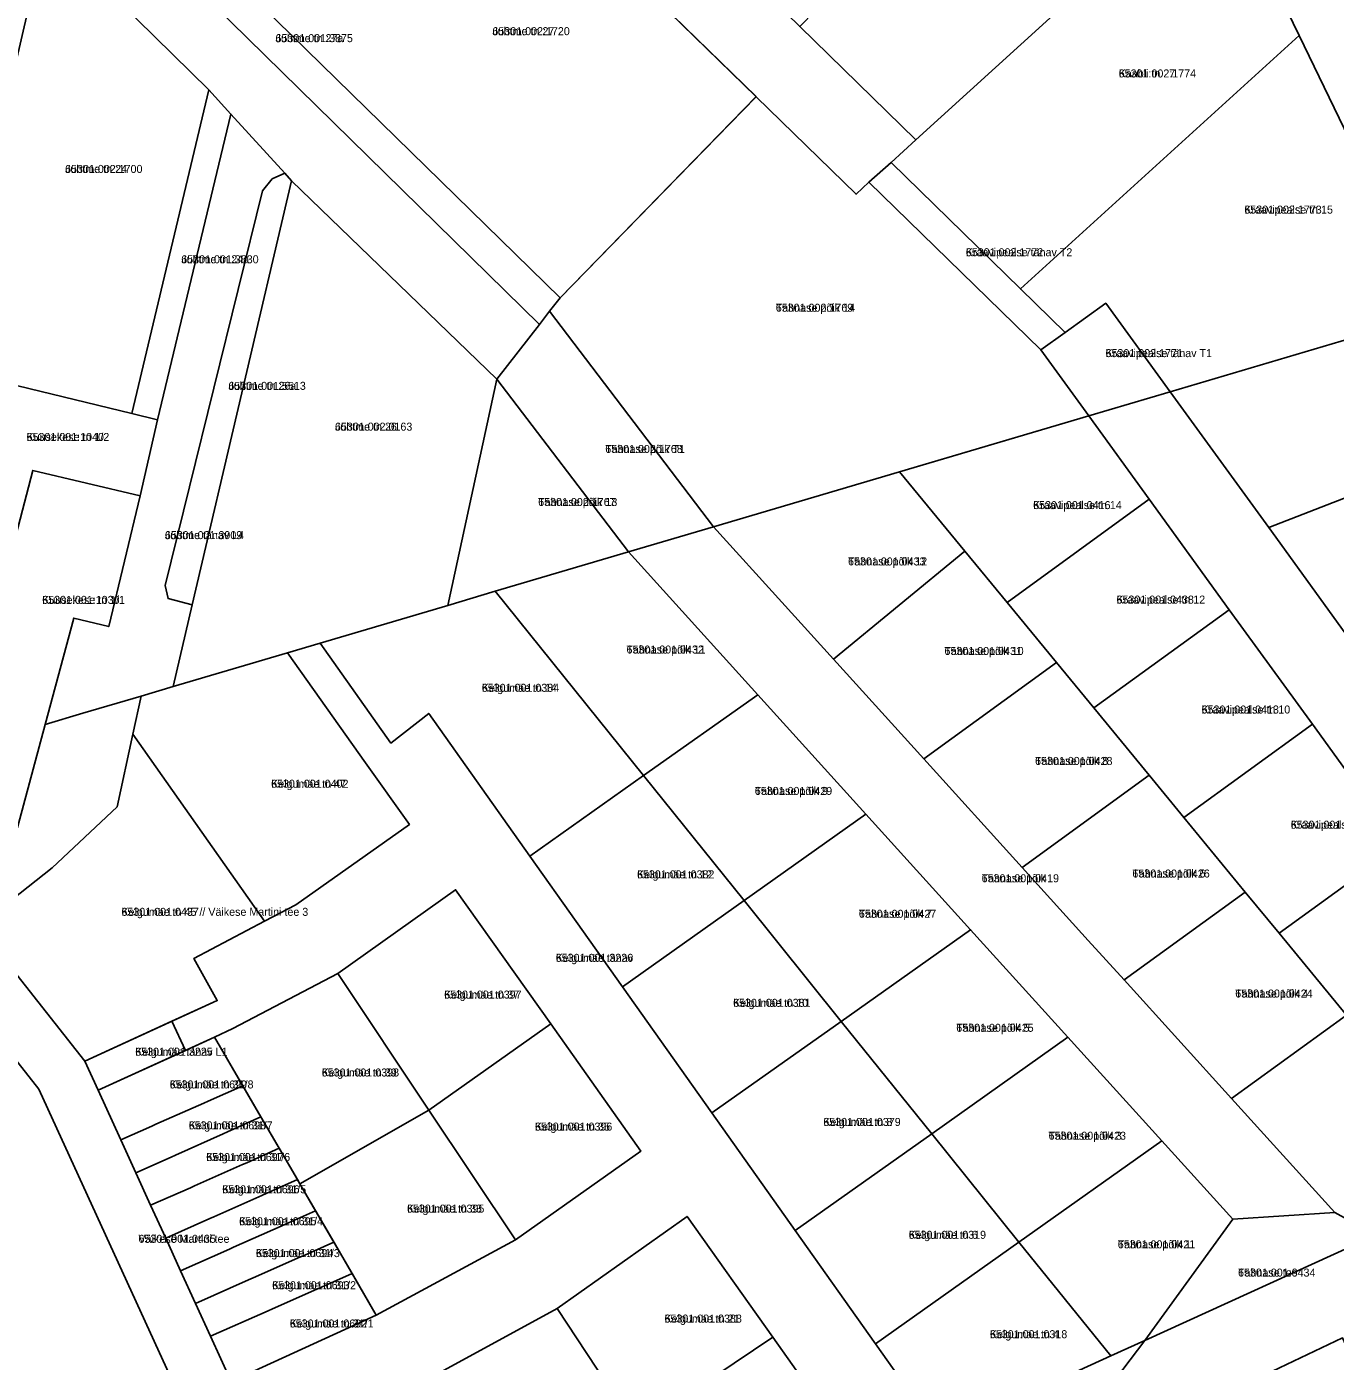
# Model space of a CAD drawing. Extents: x 543236 to 563717, y 6566033 to 6588992.
# Drawn here: x 546441.8 to 546687, y 6585249.2 to 6585499.3 of the extents above; entities that cross this region are included whole.
import ezdxf

# ---------------------------------------------------------------- set-up
doc = ezdxf.new("R2010")
doc.units = 0
for name, color, linetype in [('L_AADRESS', 7, 'Continuous'), ('PIIR', 7, 'Continuous'), ('TUNNUS', 7, 'Continuous')]:
    doc.layers.add(name, color=color, linetype=linetype)

msp = doc.modelspace()

# ---------------------------------------------------------------- linework, layer by layer
at = {"layer": 'PIIR'}
for points in [[(546727.56, 6585734.34), (546736.38, 6585744.23), (546742.19, 6585738.52), (547036.09, 6585449.99), (546820.76, 6585258.14), (546786.32, 6585314.76), (546705.5, 6585445.49), (546680.25, 6585497.64), (546664.84, 6585529.42), (546597.49, 6585563.12), (546613.01, 6585604.01)], [(546357.12, 6585624.43), (546359.63, 6585618.5), (546403.76, 6585575.17), (546410.64, 6585568.43), (546473.54, 6585506.66), (546537.87, 6585443.5), (546529.9, 6585433.25), (546491.44, 6585470.41), (546490.13, 6585471.85), (546480.05, 6585482.92), (546475.94, 6585487.45), (546445.52, 6585517.35), (546415.03, 6585547.94), (546403.82, 6585560.18), (546386.95, 6585577.03), (546377.64, 6585586.13), (546368.4, 6585595.16), (546359.11, 6585604.18), (546354.05, 6585609.18), (546349.17, 6585611.38)], [(546473.54, 6585506.66), (546513.47, 6585549.28), (546516.06, 6585546.9), (546483.31, 6585511.95), (546480.25, 6585508.68), (546541.76, 6585448.5), (546539.77, 6585445.95), (546537.87, 6585443.5)], [(546516.06, 6585546.9), (546578.48, 6585486.19), (546541.76, 6585448.5), (546480.25, 6585508.68), (546483.31, 6585511.95)], [(546628.84, 6585542.5), (546653.19, 6585518.82), (546608.42, 6585478.09), (546586.66, 6585499.3), (546620.46, 6585533.91)], [(546603.76, 6585473.84), (546608.42, 6585478.09), (546653.19, 6585518.82), (546664.84, 6585529.42), (546680.25, 6585497.64), (546628, 6585450.13)], [(546428.12, 6585448.52), (546422.02, 6585461.28), (546433.75, 6585466.89), (546445.52, 6585517.35), (546475.94, 6585487.45), (546461.46, 6585426.8), (546435.69, 6585433.02)], [(546628, 6585450.13), (546680.25, 6585497.64), (546705.5, 6585445.49), (546701.61, 6585444.34), (546656.07, 6585430.87), (546644, 6585447.47), (546636.37, 6585441.96)], [(546461.46, 6585426.8), (546475.94, 6585487.45), (546480.05, 6585482.92), (546466.3, 6585425.58)], [(546578.47, 6585486.17), (546597.22, 6585467.9), (546599.63, 6585470.14), (546631.85, 6585438.7), (546640.82, 6585426.36), (546605.38, 6585415.88), (546570.52, 6585405.57), (546539.77, 6585445.95), (546541.76, 6585448.5)], [(546480.05, 6585482.92), (546490.13, 6585471.85), (546487.8, 6585470.78), (546485.99, 6585468.5), (546467.75, 6585394.53), (546468.29, 6585392.11), (546472.81, 6585390.95), (546469.21, 6585375.61), (546463.23, 6585373.84), (546452.31, 6585370.61), (546445.23, 6585368.52), (546450.6, 6585388.45), (546457.16, 6585386.87), (546463.02, 6585411.39), (546466.3, 6585425.58)], [(546599.63, 6585470.14), (546603.76, 6585473.84), (546628, 6585450.13), (546636.37, 6585441.96), (546631.85, 6585438.7)], [(546491.44, 6585470.41), (546472.81, 6585390.95), (546468.29, 6585392.11), (546467.75, 6585394.53), (546485.99, 6585468.5), (546487.8, 6585470.78), (546490.13, 6585471.85)], [(546491.44, 6585470.41), (546529.9, 6585433.25), (546520.72, 6585390.84), (546496.76, 6585383.76), (546490.68, 6585381.96), (546469.21, 6585375.61), (546472.81, 6585390.95)], [(546539.77, 6585445.95), (546570.52, 6585405.57), (546554.56, 6585400.85), (546529.9, 6585433.25), (546537.87, 6585443.5)], [(546631.85, 6585438.7), (546636.37, 6585441.96), (546644, 6585447.47), (546656.07, 6585430.87), (546640.82, 6585426.36)], [(546656.07, 6585430.87), (546701.61, 6585444.34), (546715.75, 6585421.44), (546674.54, 6585405.4)], [(546529.9, 6585433.25), (546554.56, 6585400.85), (546529.59, 6585393.47), (546520.72, 6585390.84)], [(546426.36, 6585352.75), (546417.23, 6585361.97), (546435.69, 6585433.02), (546461.46, 6585426.8), (546466.3, 6585425.58), (546463.02, 6585411.39), (546442.91, 6585416.14)], [(546640.82, 6585426.36), (546656.07, 6585430.87), (546674.54, 6585405.4), (546692.13, 6585381.14), (546711.01, 6585355.1), (546730.57, 6585328.13), (546751.73, 6585298.95), (546737.81, 6585292.59), (546716.82, 6585321.54), (546699.19, 6585345.85), (546682.73, 6585368.55), (546667.16, 6585390.03), (546652.17, 6585410.71)], [(546605.38, 6585415.88), (546613.6, 6585418.31), (546640.82, 6585426.36), (546652.17, 6585410.71), (546625.52, 6585391.39), (546617.61, 6585401.01)], [(546674.54, 6585405.4), (546715.75, 6585421.44), (546729.96, 6585398.42), (546692.13, 6585381.14)], [(546426.36, 6585352.75), (546442.91, 6585416.14), (546463.02, 6585411.39), (546457.16, 6585386.87), (546450.6, 6585388.45), (546445.23, 6585368.52), (546440.03, 6585349.21)], [(546570.52, 6585405.57), (546605.38, 6585415.88), (546617.61, 6585401.01), (546592.99, 6585380.76), (546583.3, 6585391.46)], [(546625.52, 6585391.39), (546652.17, 6585410.71), (546667.16, 6585390.03), (546641.77, 6585371.63), (546634.78, 6585380.13)], [(546554.56, 6585400.85), (546564.14, 6585403.68), (546570.52, 6585405.57), (546583.3, 6585391.46), (546592.99, 6585380.76), (546609.9, 6585362.08), (546628.33, 6585341.73), (546640.72, 6585328.05), (546647.43, 6585320.64), (546667.55, 6585298.42), (546686.92, 6585277.02), (546667.82, 6585275.77), (546654.5, 6585290.48), (546636.92, 6585309.89), (546618.67, 6585330.05), (546599.07, 6585351.7), (546578.79, 6585374.1)], [(546529.59, 6585393.47), (546554.56, 6585400.85), (546578.79, 6585374.1), (546557.38, 6585358.92)], [(546592.99, 6585380.76), (546617.61, 6585401.01), (546625.52, 6585391.39), (546634.78, 6585380.13), (546609.9, 6585362.08)], [(546496.76, 6585383.76), (546520.72, 6585390.84), (546529.59, 6585393.47), (546557.38, 6585358.92), (546536.09, 6585343.83), (546517.13, 6585370.58), (546510.03, 6585365.03)], [(546641.77, 6585371.63), (546667.16, 6585390.03), (546682.73, 6585368.55), (546658.66, 6585351.1), (546652.15, 6585359.01)], [(546469.21, 6585375.61), (546490.68, 6585381.96), (546505.29, 6585361.35), (546513.5, 6585349.77), (546492.22, 6585334.69), (546486.37, 6585331.62), (546461.69, 6585366.71), (546463.23, 6585373.84)], [(546609.9, 6585362.08), (546634.78, 6585380.13), (546641.77, 6585371.63), (546652.15, 6585359.01), (546628.33, 6585341.73)], [(546557.38, 6585358.92), (546578.79, 6585374.1), (546599.07, 6585351.7), (546576.22, 6585335.5)], [(546658.66, 6585351.1), (546682.73, 6585368.55), (546699.19, 6585345.85), (546676.5, 6585329.4), (546670.15, 6585337.11)], [(546432.72, 6585330.71), (546446.56, 6585341.62), (546458.76, 6585353.08), (546461.69, 6585366.71), (546486.37, 6585331.62), (546473.13, 6585324.68), (546477.51, 6585316.78), (546452.66, 6585305.43)], [(546536.09, 6585343.83), (546557.38, 6585358.92), (546576.22, 6585335.5), (546553.44, 6585319.36)], [(546628.33, 6585341.73), (546652.15, 6585359.01), (546658.66, 6585351.1), (546670.15, 6585337.11), (546647.43, 6585320.64), (546640.72, 6585328.05)], [(546576.22, 6585335.5), (546599.07, 6585351.7), (546618.67, 6585330.05), (546594.43, 6585312.87)], [(546676.5, 6585329.4), (546699.19, 6585345.85), (546716.82, 6585321.54), (546695.61, 6585306.16), (546689.11, 6585314.06)], [(546500.07, 6585321.87), (546522.17, 6585337.53), (546539.98, 6585312.41), (546517.17, 6585296.24)], [(546647.43, 6585320.64), (546670.15, 6585337.11), (546676.5, 6585329.4), (546689.11, 6585314.06), (546667.55, 6585298.42)], [(546553.44, 6585319.36), (546576.22, 6585335.5), (546594.43, 6585312.87), (546570.21, 6585295.7)], [(546318.59, 6585170.56), (546277.41, 6585232.67), (546295.29, 6585243.78), (546353.02, 6585262.32), (546356.16, 6585263.99), (546367.4, 6585272.86), (546373.91, 6585264.71), (546390.11, 6585277.48), (546374.24, 6585297.35), (546418.67, 6585332.37), (546444.07, 6585300.18), (546471.39, 6585240.4)], [(546594.43, 6585312.87), (546618.67, 6585330.05), (546636.92, 6585309.89), (546611.39, 6585291.79)], [(546476.96, 6585309.93), (546480.41, 6585311.56), (546500.07, 6585321.87), (546517.17, 6585296.24), (546492.96, 6585282.45), (546492.13, 6585283.87), (546485.3, 6585295.61)], [(546667.55, 6585298.42), (546689.11, 6585314.06), (546695.61, 6585306.16), (546710.65, 6585287.87), (546702.96, 6585284.36), (546707.65, 6585278.8), (546694.59, 6585272.83), (546686.92, 6585277.02)], [(546469, 6585312.9), (546471.56, 6585307.42), (546455.16, 6585299.97), (546452.66, 6585305.43)], [(546517.17, 6585296.24), (546539.98, 6585312.41), (546556.89, 6585288.55), (546533.41, 6585271.91)], [(546570.21, 6585295.7), (546594.43, 6585312.87), (546611.39, 6585291.79), (546585.83, 6585273.67)], [(546455.16, 6585299.97), (546476.96, 6585309.93), (546482.29, 6585300.77), (546475.79, 6585297.9), (546474.97, 6585297.54), (546465.99, 6585293.58), (546465.21, 6585293.24), (546459.4, 6585290.68)], [(546611.39, 6585291.79), (546636.92, 6585309.89), (546654.5, 6585290.48), (546627.72, 6585271.49)], [(546459.4, 6585290.68), (546465.21, 6585293.24), (546465.99, 6585293.58), (546474.97, 6585297.54), (546475.79, 6585297.9), (546482.29, 6585300.77), (546485.68, 6585294.95), (546479.43, 6585292.16), (546478.63, 6585291.8), (546469.65, 6585287.8), (546468.84, 6585287.44), (546462.23, 6585284.49)], [(546492.96, 6585282.45), (546517.17, 6585296.24), (546533.41, 6585271.91), (546507.3, 6585257.82), (546498.96, 6585272.15)], [(546462.23, 6585284.49), (546468.84, 6585287.44), (546469.65, 6585287.8), (546478.63, 6585291.8), (546479.43, 6585292.16), (546485.68, 6585294.95), (546489.1, 6585289.08), (546483.03, 6585286.38), (546482.23, 6585286.03), (546473.26, 6585282.04), (546472.47, 6585281.69), (546465, 6585278.42)], [(546585.83, 6585273.67), (546611.39, 6585291.79), (546627.72, 6585271.49), (546600.86, 6585252.46)], [(546465, 6585278.42), (546472.47, 6585281.69), (546473.26, 6585282.04), (546482.23, 6585286.03), (546483.03, 6585286.38), (546489.1, 6585289.08), (546492.51, 6585283.22), (546486.67, 6585280.61), (546485.86, 6585280.25), (546476.88, 6585276.25), (546476.1, 6585275.9), (546467.84, 6585272.22)], [(546627.72, 6585271.49), (546654.5, 6585290.48), (546667.82, 6585275.77), (546651.34, 6585253.06), (546644.94, 6585250.18)], [(546467.84, 6585272.22), (546476.1, 6585275.9), (546476.88, 6585276.25), (546485.86, 6585280.25), (546486.67, 6585280.61), (546492.51, 6585283.22), (546492.96, 6585282.45), (546495.92, 6585277.36), (546490.3, 6585274.86), (546489.49, 6585274.5), (546480.57, 6585270.53), (546479.76, 6585270.17), (546470.63, 6585266.11)], [(546470.63, 6585266.11), (546479.76, 6585270.17), (546480.57, 6585270.53), (546489.49, 6585274.5), (546490.3, 6585274.86), (546495.92, 6585277.36), (546499.35, 6585271.48), (546493.92, 6585269.07), (546493.09, 6585268.71), (546484.22, 6585264.78), (546483.38, 6585264.41), (546473.42, 6585260.01)], [(546541.2, 6585259.07), (546565.55, 6585276.33), (546581.62, 6585253.67), (546556.08, 6585236.52)], [(546667.82, 6585275.77), (546686.92, 6585277.02), (546694.59, 6585272.83), (546651.35, 6585253.07)], [(546473.42, 6585260.01), (546483.38, 6585264.41), (546484.22, 6585264.78), (546493.09, 6585268.71), (546493.92, 6585269.07), (546499.35, 6585271.48), (546502.76, 6585265.61), (546497.58, 6585263.32), (546496.73, 6585262.94), (546487.83, 6585259), (546487.02, 6585258.64), (546476.23, 6585253.86)], [(546600.86, 6585252.46), (546627.72, 6585271.49), (546644.94, 6585250.18), (546612.87, 6585235.5)], [(546476.23, 6585253.86), (546487.02, 6585258.64), (546487.83, 6585259), (546496.73, 6585262.94), (546497.58, 6585263.32), (546502.76, 6585265.61), (546507.3, 6585257.82), (546480.1, 6585245.39)], [(546515.89, 6585245.26), (546541.2, 6585259.07), (546556.08, 6585236.52), (546527.22, 6585221.73), (546524.65, 6585227.04), (546518.8, 6585239.19)], [(546556.08, 6585236.52), (546581.62, 6585253.67), (546599, 6585229.14), (546569.76, 6585215.78)], [(546666.1, 6585242.92), (546688.38, 6585253.53), (546709.5, 6585207.29), (546705.24, 6585205.35), (546664.42, 6585186.71), (546620.75, 6585166.75), (546587.35, 6585151.57), (546628.58, 6585197.73)], [(546644.94, 6585250.18), (546651.34, 6585253.06), (546625.03, 6585218.39), (546612.87, 6585235.5)]]:
    msp.add_lwpolyline(points, close=True, dxfattribs=at)
for points in [[(546429.2, 6585651.31), (546446.09, 6585635.89), (546480.52, 6585604.45), (546496.46, 6585587.83), (546507.64, 6585576.47), (546542.3, 6585542.61), (546586.66, 6585499.3), (546608.42, 6585478.09), (546603.76, 6585473.84), (546599.63, 6585470.14), (546597.22, 6585467.9), (546578.47, 6585486.17), (546516.06, 6585546.9), (546513.47, 6585549.28), (546510.93, 6585551.71), (546492.93, 6585569.07), (546491.01, 6585572.73), (546486.75, 6585576.6), (546484.16, 6585577.84), (546450.15, 6585610.33), (546444.29, 6585617.2), (546369.81, 6585685.23)], [(546480.1, 6585245.39), (546507.3, 6585257.82), (546533.41, 6585271.91), (546556.89, 6585288.55), (546539.98, 6585312.41), (546522.17, 6585337.53), (546500.07, 6585321.87), (546480.41, 6585311.56), (546476.96, 6585309.93), (546471.56, 6585307.42), (546469, 6585312.9), (546477.51, 6585316.78), (546473.13, 6585324.68), (546486.37, 6585331.62), (546492.22, 6585334.69), (546513.5, 6585349.77), (546505.29, 6585361.35), (546490.68, 6585381.96), (546496.76, 6585383.76), (546510.03, 6585365.03), (546517.13, 6585370.58), (546536.09, 6585343.83), (546553.44, 6585319.36), (546570.21, 6585295.7), (546585.83, 6585273.67), (546600.86, 6585252.46), (546612.87, 6585235.5)], [(546440.03, 6585349.21), (546445.23, 6585368.52), (546452.31, 6585370.61), (546463.23, 6585373.84), (546461.69, 6585366.71), (546458.76, 6585353.08), (546446.56, 6585341.62), (546432.72, 6585330.71), (546452.66, 6585305.43), (546455.16, 6585299.97), (546459.4, 6585290.68), (546462.23, 6585284.49), (546465, 6585278.42), (546467.84, 6585272.22), (546470.63, 6585266.11), (546473.42, 6585260.01), (546476.23, 6585253.86), (546480.1, 6585245.39)], [(546471.39, 6585240.4), (546444.07, 6585300.18), (546418.67, 6585332.37)], [(546599, 6585229.14), (546581.62, 6585253.67), (546565.55, 6585276.33), (546541.2, 6585259.07), (546515.89, 6585245.26)], [(546625.03, 6585218.39), (546651.34, 6585253.06), (546694.59, 6585272.83)], [(546688.38, 6585253.53), (546666.1, 6585242.92)]]:
    msp.add_lwpolyline(points, dxfattribs=at)

# ---------------------------------------------------------------- texts
at = {"layer": 'L_AADRESS'}
for s, p in [('Juhtme tn 27', (546529.06, 6585497.7)), ('Juhtme tn 27a', (546488.41, 6585496.39)), ('Kaabli tn 27', (546646.43, 6585489.78)), ('Juhtme tn 24', (546448.98, 6585471.88)), ('Kraavipealse tn 15', (546669.97, 6585464.26)), ('Juhtme tn 24a', (546470.75, 6585454.95)), ('Kraavipealse tänav T2', (546617.78, 6585456.27)), ('Tähnase põik 14', (546582.17, 6585445.87)), ('Kraavipealse tänav T1', (546643.96, 6585437.36)), ('Juhtme tn 26a', (546479.59, 6585431.23)), ('Kuusekese tn 1/2', (546441.76, 6585421.65)), ('Juhtme tn 26', (546499.55, 6585423.58)), ('Tähnase põik T1', (546550.21, 6585419.4)), ('Tähnase põik 13', (546537.64, 6585409.46)), ('Kraavipealse tn 14', (546630.39, 6585408.88)), ('Juhtme tänav L4', (546467.68, 6585403.25)), ('Tähnase põik 12', (546595.71, 6585398.32)), ('Kuusekese tn 1/1', (546444.69, 6585391.12)), ('Kraavipealse tn 12', (546646.02, 6585391.17)), ('Tähnase põik 11', (546554.19, 6585381.81)), ('Tähnase põik 10', (546613.78, 6585381.54)), ('Kelgumäe tn 14', (546527.07, 6585374.64)), ('Kraavipealse tn 10', (546661.96, 6585370.57)), ('Tähnase põik 8', (546630.76, 6585360.93)), ('Kelgumäe tn 47', (546487.59, 6585356.66)), ('Tähnase põik 9', (546578.23, 6585355.31)), ('Kraavipealse tn 8', (546678.66, 6585348.98)), ('Kelgumäe tn 12', (546556.16, 6585339.67)), ('Tähnase põik 6', (546648.99, 6585339.83)), ('Tähnase põik', (546620.74, 6585338.94)), ('Kelgumäe tn 45 // Väikese Martini tee 3', (546459.54, 6585332.65)), ('Tähnase põik 7', (546597.73, 6585332.29)), ('Kelgumäe tänav', (546540.93, 6585324.03)), ('Kelgumäe tn 37', (546520.02, 6585317.14)), ('Tähnase põik 4', (546668.27, 6585317.34)), ('Kelgumäe tn 10', (546574.17, 6585315.6)), ('Tähnase põik 5', (546615.99, 6585310.92)), ('Kelgumäe tänav L1', (546462.13, 6585306.43)), ('Kelgumäe tn 39', (546497.07, 6585302.54)), ('Kelgumäe tn 31/8', (546468.57, 6585300.3)), ('Kelgumäe tn 31/7', (546472.15, 6585292.63)), ('Kelgumäe tn 35', (546537.03, 6585292.4)), ('Kelgumäe tn 8', (546591.07, 6585293.27)), ('Tähnase põik 3', (546633.29, 6585290.69)), ('Kelgumäe tn 31/6', (546475.43, 6585286.69)), ('Kelgumäe tn 31/5', (546478.43, 6585280.65)), ('Kelgumäe tn 33', (546513.05, 6585277.03)), ('Kelgumäe tn 31/4', (546481.59, 6585274.66)), ('Kelgumäe tn 6', (546607.07, 6585272.12)), ('Väikese Martini tee', (546462.73, 6585271.37)), ('Tähnase põik 1', (546646.26, 6585270.33)), ('Kelgumäe tn 31/3', (546484.73, 6585268.69)), ('Tähnase tee', (546668.8, 6585265.04)), ('Kelgumäe tn 31/2', (546487.78, 6585262.67)), ('Kelgumäe tn 21', (546561.31, 6585256.42)), ('Kelgumäe tn 31/1', (546491.08, 6585255.5)), ('Kelgumäe tn 4', (546622.29, 6585253.49))]:
    msp.add_text(s, height=1.5, dxfattribs=at).set_placement(p)
at = {"layer": 'TUNNUS'}
for s, p in [('65301:002:1720', (546529.06, 6585497.7)), ('65301:001:3875', (546488.41, 6585496.39)), ('65301:002:1774', (546646.43, 6585489.78)), ('65301:002:1700', (546448.98, 6585471.88)), ('65301:002:1773', (546669.97, 6585464.26)), ('65301:001:3830', (546470.75, 6585454.95)), ('65301:002:1772', (546617.78, 6585456.27)), ('65301:002:1769', (546582.17, 6585445.87)), ('65301:002:1771', (546643.96, 6585437.36)), ('65301:001:5513', (546479.59, 6585431.23)), ('65301:001:1040', (546441.76, 6585421.65)), ('65301:002:0163', (546499.55, 6585423.58)), ('65301:002:1768', (546550.21, 6585419.4)), ('65301:002:1767', (546537.64, 6585409.46)), ('65301:001:0416', (546630.39, 6585408.88)), ('65301:001:3909', (546467.68, 6585403.25)), ('65301:001:0433', (546595.71, 6585398.32)), ('65301:001:1030', (546444.69, 6585391.12)), ('65301:001:0438', (546646.02, 6585391.17)), ('65301:001:0432', (546554.19, 6585381.81)), ('65301:001:0431', (546613.78, 6585381.54)), ('65301:001:0384', (546527.07, 6585374.64)), ('65301:001:0413', (546661.96, 6585370.57)), ('65301:001:0428', (546630.76, 6585360.93)), ('65301:001:0402', (546487.59, 6585356.66)), ('65301:001:0429', (546578.23, 6585355.31)), ('65301:001:0409', (546678.66, 6585348.98)), ('65301:001:0382', (546556.16, 6585339.67)), ('65301:001:0426', (546648.99, 6585339.83)), ('65301:001:0419', (546620.74, 6585338.94)), ('65301:001:0437', (546459.54, 6585332.65)), ('65301:001:0427', (546597.73, 6585332.29)), ('65301:001:3226', (546540.93, 6585324.03)), ('65301:001:0397', (546520.02, 6585317.14)), ('65301:001:0424', (546668.27, 6585317.34)), ('65301:001:0381', (546574.17, 6585315.6)), ('65301:001:0425', (546615.99, 6585310.92)), ('65301:001:3225', (546462.13, 6585306.43)), ('65301:001:0398', (546497.07, 6585302.54)), ('65301:001:0699', (546468.57, 6585300.3)), ('65301:001:0698', (546472.15, 6585292.63)), ('65301:001:0396', (546537.03, 6585292.4)), ('65301:001:0379', (546591.07, 6585293.27)), ('65301:001:0423', (546633.29, 6585290.69)), ('65301:001:0697', (546475.43, 6585286.69)), ('65301:001:0696', (546478.43, 6585280.65)), ('65301:001:0395', (546513.05, 6585277.03)), ('65301:001:0695', (546481.59, 6585274.66)), ('65301:001:0319', (546607.07, 6585272.12)), ('65301:001:0435', (546462.73, 6585271.37)), ('65301:001:0421', (546646.26, 6585270.33)), ('65301:001:0694', (546484.73, 6585268.69)), ('65301:001:0434', (546668.8, 6585265.04)), ('65301:001:0693', (546487.78, 6585262.67)), ('65301:001:0692', (546491.08, 6585255.5)), ('65301:001:0388', (546561.31, 6585256.42)), ('65301:001:0318', (546622.29, 6585253.49))]:
    msp.add_text(s, height=1.5, dxfattribs=at).set_placement(p)

doc.saveas('drawing.dxf')
